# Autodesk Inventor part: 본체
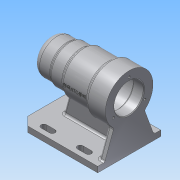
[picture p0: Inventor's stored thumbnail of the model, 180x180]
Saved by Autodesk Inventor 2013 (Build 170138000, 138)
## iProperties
Created: 2017-09
Part Number: 본체
Material: 알루미늄 6061
Document SubType Name: Modeling
Designer: Administrator
Mass: 696.155 g
Surface Area: 708.741 cm^2
Volume: 256.884 cm^3
Density: 2.71 g/cm^3
Author: Administrator
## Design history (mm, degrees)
sketch "스케치1"
  geometry: L1 (-56, 45)-(56, 45); L2 (56, 45)-(56, -45); L3 (56, -45)-(-56, -45); L4 (-56, -45)-(-56, 45); 3 further points
  constraints: 8 end point, 2 midpoint, 2 parallel, 1 horizontal, 1 horizontal alignment, 1 perpendicular, 1 vertical alignment
  dimensions: "d0" = 90 distance of L1.end L2.end; "d2" = 112 distance of L1.start L1.end
extrude "돌출1" new body sketch "스케치1" distance "d3" = 8; taper "d4" = 0 deg
sketch "스케치2"
  geometry: L1 (-56, 70)-(56, 70); L2 (-56, 0)-(56, 0) reference; L3 (56, 70)-(56, 95); L4 (56, 95)-(31, 95); L5 (31, 95)-(31, 97); L6 (31, 97)-(11, 97); L7 (11, 97)-(11, 100); L8 (11, 100)-(-28, 100); L9 (-28, 100)-(-28, 104); L10 (-28, 104)-(-56, 104); L11 (-56, 104)-(-56, 70); 2 further points
  constraints: 20 end point, 7 parallel, 2 perpendicular, 1 horizontal, 1 midpoint, 1 vertical alignment
  dimensions: "d5" = 112 distance of L1.start L1.end; "d7" = 70 distance from line of L2 L1.end; "d15" = 68 diameter of L10 L1; "d16" = 60 diameter of L8 L1; "d17" = 54 diameter of L6 L1; "d18" = 50 diameter of L4 L1; "d19" = 25 distance of L3.end L4.end; "d20" = 45 distance from line of L3 L6.end; "d21" = 84 distance between parallel lines of L3 L9
revolve "회전1" sketch "스케치2" stored, may be unused: angle "d22" = 90 deg
sketch "스케치4"
  geometry: L1 (56, 8)-(-56, 8) reference; L2 (34, 8)-(17.086, 71.123); L3 (17.086, 71.123)-(-56, 71.123); L4 (-56, 71.123)-(-56, 8); 1 further point
  constraints: 6 end point, 1 parallel, 1 perpendicular, 1 point on line
  dimensions: "d37" = 22 distance of L1.start L2.start; "d38" = 105 deg angle of L1 L2
extrude "돌출2" join sketch "스케치4" stored distance "d39" = 8; taper "d40" = 0 deg
sketch "스케치5"
  geometry: L1 (0, 90)-(0, 0) reference; L2 (0, 90)-(-8, 90) reference; L3 (-8, 49)-(-8, 90) reference; L4 (-8, 0)-(-8, 41) reference; L5 (0, 0)-(-8, 0) reference; L6 (-8, 80)-(-70, 57.434); L7 (-70, 57.434)-(-70, 32.566); L8 (-70, 32.566)-(-8, 10); 1 further point
  constraints: 6 end point, 2 point on line, 1 equal length, 1 vertical
  dimensions: "d41" = 10 distance of L2.end L6.start; "d42" = 10 distance of L4.start L8.end; "d43" = 110 deg angle of L3 L6; "d44" = 62 distance between parallel lines of L4 L7
extrude "돌출3" join sketch "스케치5" distance "d45" = 8; taper "d46" = 0 deg
sketch "스케치3"
  geometry: L1 (-56, 36)-(-56, 104) reference; L2 (56, 45)-(56, 95) reference; L3 (-56, 70)-(56, 70); L4 (50, 70)-(50, 80.5); L5 (50, 80.5)-(47, 80.5); L6 (47, 80.5)-(47, 86); L7 (47, 86)-(43, 86); L8 (43, 86)-(43, 87.5); L9 (43, 87.5)-(25, 87.5); L10 (25, 87.5)-(25, 91); L11 (25, 91)-(13, 91); L12 (13, 91)-(13, 94); L13 (13, 94)-(-41, 94); L14 (-41, 94)-(-41, 91); L15 (-41, 91)-(-56, 91); 2 further points
  constraints: 26 end point, 10 parallel, 3 midpoint, 2 perpendicular, 2 point on line, 1 horizontal, 1 vertical alignment
  dimensions: "d23" = 42 diameter of L15 L3; "d25" = 48 diameter of L13 L3; "d26" = 42 diameter of L11 L3; "d27" = 35 diameter of L9 L3; "d28" = 32 diameter of L7 L3; "d29" = 21 diameter of L5 L3; "d30" = 15 distance of L14.end L15.end; "d31" = 54 distance of L12.end L13.end; "d32" = 12 distance of L10.end L11.end; "d33" = 18 distance of L8.end L9.end; "d34" = 3 distance of L4.end L5.end; "d35" = 4 distance of L6.end L7.end
revolve "회전2" sketch "스케치3" stored, may be unused: angle "d36" = 90 deg
sketch "스케치6"
  geometry: L1 (56, -45)-(56, -35) reference; L2 (-34, 4)-(48, 4) reference; L3 (-32, 30)-(-20, 30); L4 (-20, 38)-(-32, 38); L5 (32, 38)-(20, 38); L6 (20, 30)-(32, 30); L7 (32, -30)-(20, -30); L8 (20, -38)-(32, -38); L9 (-20, -30)-(-32, -30); L10 (-32, -38)-(-20, -38); A1 r 4 centre (-20, 34) between (-20, 30) and (-20, 38); A2 r 4 centre (-32, 34) between (-32, 38) and (-32, 30); A3 r 4 centre (32, 34) between (32, 30) and (32, 38); A4 r 4 centre (20, 34) between (20, 38) and (20, 30); A5 r 4 centre (32, -34) between (32, -38) and (32, -30); A6 r 4 centre (20, -34) between (20, -30) and (20, -38); A7 r 4 centre (-20, -34) between (-20, -38) and (-20, -30); A8 r 4 centre (-32, -34) between (-32, -30) and (-32, -38); 1 further point
  constraints: 16 end point, 16 point on circle, 16 tangent, 8 centre point, 5 parallel, 2 horizontal alignment, 2 vertical alignment
  dimensions: "d47" = 12 distance of A1.centre A2.centre; "d49" = 4 radius of A2; "d50" = 34 vertical distance of point (0, 0) A2.centre; "d51" = 12 distance of A3.centre A4.centre; "d52" = 4 radius of A4; "d53" = 12 distance of A5.centre A6.centre; "d54" = 4 radius of A6; "d55" = 12 distance of A7.centre A8.centre; "d56" = 4 radius of A8; "d57" = 24 distance from line of L1 A5.centre; "d58" = 40 distance of A6.centre A7.centre; "d59" = 34 vertical distance of point (0, 0) A8.centre
extrude "돌출4" cut sketch "스케치6" distance "d60" = 15; taper "d61" = 0 deg
sketch "스케치7" dims "d62" = 52
  geometry: C1 r 21 at (-70, 45) reference; A1 r 34 centre (-70, 45) between (-43.992, 66.9) and (-43.992, 23.1) reference; 3 further points
  constraints: 2 horizontal alignment, 1 coincident, 2 other
hole "구멍1" sketch "스케치7" at (-96, 45) diameter "d64" = 3.242; stored, may be unused: countersink angle "d68" = 90 deg, drill point angle "d70" = 118 deg; dims "d65" = 8, "d66" = 4, "d67" = 2, "d69" = 11
chamfer "모따기1" distance "d74" = 12; stored, may be unused: second distance "d75" = 2, angle "d76" = 45 deg
chamfer "모따기2" distance "d77" = 1; stored, may be unused: second distance "d78" = 2, angle "d79" = 45 deg
fillet "모깎기1" dims "d80" = 0.3
fillet "모깎기2" dims "d81" = 3
fillet "모깎기3" dims "d82" = 3
fillet "모깎기4" dims "d83" = 9
fillet "모깎기5" dims "d84" = 3
fillet "모깎기6" dims "d85" = 3
fillet "모깎기7" dims "d86" = 3
fillet "모깎기8" dims "d87" = 3
fillet "모깎기9" dims "d88" = 3
fillet "모깎기10" dims "d89" = 3
fillet "모깎기11" dims "d90" = 3
fillet "모깎기12" dims "d91" = 3
fillet "모깎기13" dims "d92" = 3
node "작업 평면1"
node "작업 평면2"
node "작업 평면3"
sketch "스케치9"
  geometry: L1 (56, 48)-(56, 92) reference; L2 (20, 0)-(16, 0) reference; 2 further points
  constraints: 1 other
  dimensions: "d98" = 48 distance from line of L1 point (8, 70); "d99" = 70 distance from line of L2 point (8, 70)
feature "엠보싱1" sketch "스케치9" dims "d0" = 90, "d2" = 112, "d5" = 112, "d7" = 70, "d15" = 68, "d16" = 60, "d17" = 54, "d18" = 50, "d19" = 25, "d20" = 45, "d21" = 84, "d100" = 0.5, "d101" = 0
node "솔리드1"
pattern_circular "원형 패턴1" dims angle "d72" = 360 deg
other parameters: "d93" = -14.25, "d94" = -24.25
